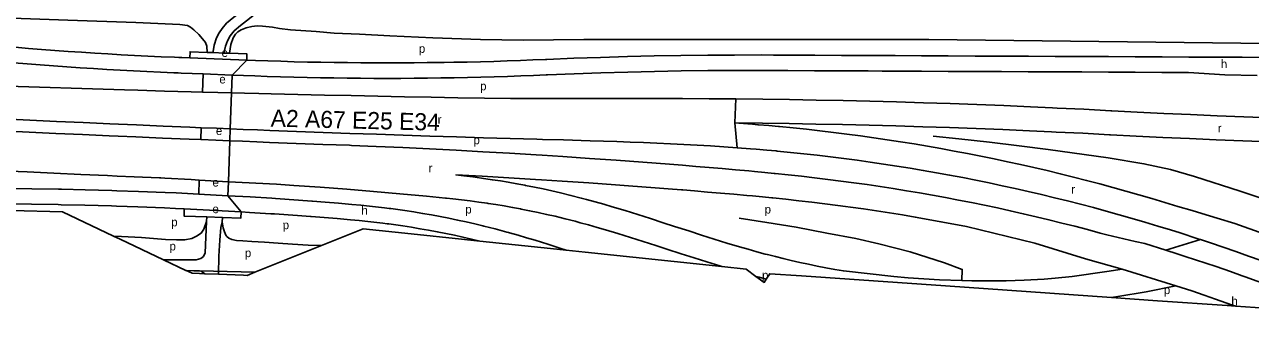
# Model space of a CAD drawing. Extents: x 161093 to 163177, y 379000 to 380904.
# Drawn here: x 162069 to 162643, y 379465 to 379601 of the extents above; entities that cross this region are included whole.
import ezdxf

# ---------------------------------------------------------------- set-up
doc = ezdxf.new("R2010")
doc.units = 0
for name, color, linetype in [('BLT_Basislijn', 7, 'Continuous'), ('BLT_Centroide', 7, 'Continuous'), ('BLT_Gemeentegrens', 7, 'Continuous'), ('BLT_Hoogspanningsmast_en_leidingen', 7, 'Continuous'), ('BLT_Straatnaam_hoofdweg', 7, 'Continuous'), ('BLT_Vlakafsluiter', 7, 'Continuous')]:
    doc.layers.add(name, color=color, linetype=linetype)

msp = doc.modelspace()

# ---------------------------------------------------------------- linework, layer by layer
at = {"layer": 'BLT_Basislijn'}
for p, q in [((162152.28, 379568.87), (162152.59, 379577.39)), ((162054.48, 379571.89), (162115.85, 379569.9)), ((162165.91, 379568.51), (162166.21, 379576.86)), ((162151.48, 379546.61), (162151.69, 379552.21)), ((162165.1, 379546.06), (162165.3, 379551.66)), ((162150.57, 379521.08), (162150.8, 379527.66)), ((162164.18, 379520.36), (162164.41, 379526.86)), ((162603.05, 379494.82), (162619.29, 379499.84)), ((162153.43, 379483.8), (162151.66, 379484.98)), ((162631.83, 379468.91), (162633.88, 379469.33))]:
    msp.add_line(p, q, dxfattribs=at)
for points in [[(162154.44, 379587.46), (162154.31, 379590.38), (162153.73, 379592.07), (162152.3, 379593.86), (162150.56, 379595.82), (162148.24, 379598.09), (162146.65, 379599.3), (162145.28, 379599.99), (162141.64, 379600.52), (162121.07, 379601.52), (162089.29, 379602.54), (162054.12, 379603.88), (162011.17, 379606.32), (161966.06, 379609.87), (161932.99, 379612.83), (161886.58, 379616.22), (161843.25, 379618.32), (161808.99, 379620.26), (161784.42, 379621.55), (161777.14, 379621.71)], [(162171.47, 379608.91), (162169.44, 379605.85), (162167, 379603.94), (162163.54, 379601.08), (162161.44, 379598.67), (162160.03, 379596.68), (162158.86, 379594.34), (162157.72, 379590.92), (162157.34, 379587.94), (162157.32, 379587.36)], [(162177.94, 379606.17), (162170.14, 379600.04), (162167.13, 379597.56), (162165.3, 379595.26), (162163.94, 379592.87), (162163, 379590.41), (162162.55, 379588.37), (162162.5, 379587.17)], [(162164.91, 379587.09), (162165.52, 379591.16), (162166.59, 379594.21), (162167.76, 379596.07), (162168.78, 379597.07), (162170.47, 379598.01), (162172.7, 379598.91), (162175.42, 379599.6), (162177.86, 379599.88), (162180.36, 379599.76), (162185.01, 379599.21), (162188.37, 379598.73), (162193.44, 379598.04), (162205.56, 379597.25), (162213.97, 379596.55), (162225.79, 379596.02), (162240.04, 379595.18), (162260.1, 379594.23), (162282.45, 379593.49), (162302.41, 379593.12), (162330.83, 379593.58), (162362.51, 379593.58), (162384.41, 379593.58), (162397.35, 379593.54), (162492.21, 379593.5), (162664.71, 379591.45)], [(162146.38, 379584.89), (162142.7, 379585.03), (162141.21, 379585.09), (162139.15, 379585.17), (162132.93, 379585.44), (162126.71, 379585.72), (162120.5, 379586.03), (162114.28, 379586.36), (162108.06, 379586.72), (162101.85, 379587.1), (162095.64, 379587.5), (162089.43, 379587.92), (162083.22, 379588.37), (162077.01, 379588.84), (162070.81, 379589.33), (162064.6, 379589.84)], [(162146.38, 379584.89), (162146.49, 379587.75), (162154.44, 379587.46)], [(162173, 379583.85), (162146.38, 379584.89)], [(162154.44, 379587.46), (162157.32, 379587.36)], [(162157.32, 379587.36), (162162.5, 379587.17)], [(162162.5, 379587.17), (162164.91, 379587.09)], [(162164.91, 379587.09), (162173.11, 379586.79), (162173, 379583.85)], [(162177.15, 379583.69), (162173, 379583.85)], [(162401.26, 379586.24), (162388.72, 379586.16), (162376.18, 379586.01), (162363.64, 379585.79), (162351.11, 379585.5), (162338.57, 379585.14), (162326.04, 379584.7), (162313.51, 379584.19), (162312.78, 379584.16), (162306.92, 379583.92), (162301.07, 379583.69), (162294.85, 379583.48), (162288.63, 379583.28), (162282.4, 379583.11), (162276.18, 379582.96), (162269.96, 379582.84), (162265.4, 379582.76), (162263.73, 379582.74), (162257.51, 379582.66), (162251.28, 379582.6), (162245.06, 379582.57), (162238.83, 379582.56), (162232.61, 379582.57), (162226.38, 379582.6), (162220.16, 379582.66), (162213.93, 379582.74), (162207.71, 379582.84), (162201.49, 379582.97), (162195.26, 379583.12), (162189.04, 379583.29), (162182.82, 379583.49), (162177.15, 379583.69)], [(162651.31, 379585.12), (162638.81, 379585.18), (162626.31, 379585.24), (162613.81, 379585.3), (162601.31, 379585.36), (162588.81, 379585.42), (162576.31, 379585.48), (162563.81, 379585.54), (162551.31, 379585.6), (162538.81, 379585.66), (162526.31, 379585.72), (162513.81, 379585.78), (162501.31, 379585.84), (162488.81, 379585.9), (162476.46, 379585.96), (162476.31, 379585.96), (162470.45, 379585.99), (162463.81, 379586.02), (162451.31, 379586.08), (162438.81, 379586.14), (162426.31, 379586.2), (162419.53, 379586.23), (162413.79, 379586.25), (162401.26, 379586.24)], [(162063.96, 379582.62), (162070.19, 379582.1), (162076.42, 379581.61), (162082.65, 379581.14), (162088.89, 379580.69), (162095.13, 379580.26), (162101.37, 379579.86), (162107.61, 379579.48), (162113.85, 379579.13), (162120.09, 379578.79), (162126.33, 379578.48), (162132.58, 379578.2), (162138.83, 379577.93), (162140.9, 379577.85), (162142.36, 379577.79), (162152.59, 379577.39)], [(162152.59, 379577.39), (162166.21, 379576.86)], [(162176.8, 379576.45), (162182.55, 379576.24), (162188.79, 379576.05), (162195.04, 379575.87), (162201.29, 379575.72), (162207.54, 379575.6), (162213.8, 379575.49), (162220.05, 379575.41), (162226.3, 379575.35), (162232.55, 379575.32), (162238.8, 379575.31), (162245.05, 379575.32), (162251.3, 379575.35), (162257.56, 379575.41), (162263.81, 379575.49), (162265.48, 379575.51), (162270.06, 379575.59), (162276.31, 379575.72), (162282.56, 379575.86), (162288.81, 379576.04), (162295.06, 379576.23), (162301.3, 379576.45), (162307.18, 379576.67), (162313.06, 379576.92), (162313.8, 379576.95), (162326.28, 379577.46), (162338.77, 379577.89), (162351.27, 379578.25), (162363.76, 379578.55), (162376.25, 379578.77), (162388.75, 379578.92), (162401.25, 379579), (162413.75, 379579), (162419.46, 379578.98), (162426.24, 379578.95), (162438.74, 379578.89), (162451.24, 379578.83), (162463.74, 379578.77), (162470.38, 379578.74), (162476.24, 379578.71), (162476.39, 379578.71), (162488.74, 379578.65), (162501.24, 379578.59), (162513.74, 379578.53), (162526.24, 379578.47), (162538.74, 379578.41), (162551.24, 379578.35), (162563.74, 379578.29), (162576.24, 379578.23), (162588.74, 379578.17), (162601.24, 379578.11), (162613.74, 379578.05), (162630.68, 379576.99), (162645.83, 379576.71)], [(162166.21, 379576.86), (162176.8, 379576.45)], [(162152.28, 379568.87), (162147.03, 379569.01), (162134.56, 379569.36), (162122.08, 379569.72), (162115.85, 379569.9)], [(162165.91, 379568.51), (162159.51, 379568.68), (162152.28, 379568.87)], [(162401.95, 379565.7), (162389.42, 379565.8), (162376.89, 379565.86), (162364.36, 379565.89), (162364.34, 379565.89), (162362.51, 379565.89), (162351.85, 379565.88), (162339.35, 379565.88), (162326.85, 379565.88), (162314.35, 379565.88), (162301.85, 379565.88), (162296.46, 379565.87), (162284.28, 379566.06), (162271.8, 379566.26), (162259.33, 379566.48), (162246.85, 379566.71), (162234.37, 379566.95), (162221.89, 379567.21), (162209.42, 379567.48), (162196.94, 379567.76), (162184.46, 379568.05), (162178.65, 379568.19), (162171.99, 379568.36), (162165.91, 379568.51)], [(162652.04, 379556.86), (162639.58, 379557.31), (162627.13, 379557.8), (162614.67, 379558.34), (162602.22, 379558.91), (162589.76, 379559.52), (162577.78, 379560.14), (162577.31, 379560.17), (162564.79, 379560.82), (162552.28, 379561.43), (162550.14, 379561.53), (162539.76, 379562), (162527.24, 379562.53), (162514.71, 379563.02), (162502.19, 379563.48), (162489.66, 379563.89), (162477.14, 379564.27), (162464.61, 379564.6), (162452.08, 379564.9), (162439.55, 379565.16), (162427.02, 379565.38), (162414.49, 379565.56), (162401.95, 379565.7)], [(162058.96, 379556.35), (162071.44, 379555.75), (162083.92, 379555.17), (162096.41, 379554.59), (162108.89, 379554.03), (162113.07, 379553.85)], [(162401.45, 379554.45), (162403.34, 379554.32), (162409.67, 379553.83), (162412.2, 379553.62), (162412.42, 379553.6), (162417.37, 379553.18), (162421.84, 379552.77), (162422.32, 379552.73), (162428.64, 379552.11), (162434.95, 379551.45), (162441.26, 379550.74), (162447.57, 379549.99), (162453.87, 379549.2), (162460.16, 379548.37), (162466.45, 379547.49), (162472.73, 379546.56), (162479, 379545.59), (162485.27, 379544.58), (162491.53, 379543.53), (162497.79, 379542.43), (162504.03, 379541.29), (162510.27, 379540.11), (162516.5, 379538.88), (162522.72, 379537.61), (162528.93, 379536.29), (162535.14, 379534.94), (162541.33, 379533.54), (162547.51, 379532.09), (162553.68, 379530.61), (162559.85, 379529.08), (162566, 379527.51), (162572.14, 379525.89), (162578.27, 379524.23), (162584.39, 379522.53), (162590.49, 379520.79), (162596.58, 379519.01), (162602.67, 379517.18), (162608.78, 379515.36), (162615.4, 379513.44), (162619.89, 379512.01), (162627.13, 379509.81), (162635.36, 379507.31)], [(162651.65, 379545.61), (162639.16, 379546.07), (162626.66, 379546.56), (162614.17, 379547.1), (162601.68, 379547.67), (162589.2, 379548.28), (162577.18, 379548.91), (162576.71, 379548.93), (162564.23, 379549.58), (162551.75, 379550.19), (162549.62, 379550.29), (162539.26, 379550.76), (162526.78, 379551.29), (162514.29, 379551.78), (162501.8, 379552.23), (162489.31, 379552.65), (162476.82, 379553.02), (162464.32, 379553.36), (162451.83, 379553.65), (162439.33, 379553.91), (162426.84, 379554.13), (162414.34, 379554.31), (162401.45, 379554.45)], [(162058.68, 379550.76), (162071.17, 379550.16), (162083.66, 379549.57), (162096.15, 379549), (162108.64, 379548.44), (162112.91, 379548.25)], [(162113.07, 379553.85), (162121.38, 379553.48), (162133.86, 379552.95), (162146.35, 379552.43), (162151.69, 379552.21)], [(162151.69, 379552.21), (162158.83, 379551.92), (162165.3, 379551.66)], [(162165.3, 379551.66), (162171.32, 379551.42), (162178, 379551.16), (162183.81, 379550.94), (162196.3, 379550.47), (162208.79, 379550.01), (162221.28, 379549.57), (162233.77, 379549.14), (162246.26, 379548.72), (162258.75, 379548.31), (162271.24, 379547.92), (162283.73, 379547.54), (162296.22, 379547.18), (162308.71, 379546.83), (162311.43, 379546.75), (162321.21, 379546.48), (162333.71, 379546.12), (162346.21, 379545.72), (162352.47, 379545.49), (162358.72, 379545.25), (162364.98, 379544.99), (162371.23, 379544.71), (162377.48, 379544.4), (162383.74, 379544.06), (162389.99, 379543.69), (162396.25, 379543.29), (162402.5, 379542.85)], [(162112.91, 379548.25), (162121.13, 379547.89), (162133.62, 379547.35), (162146.12, 379546.83), (162151.48, 379546.61)], [(162151.48, 379546.61), (162158.61, 379546.32), (162165.1, 379546.06)], [(162165.1, 379546.06), (162171.1, 379545.83), (162177.78, 379545.57), (162183.6, 379545.34), (162196.09, 379544.87), (162208.58, 379544.42), (162221.08, 379543.97), (162222.08, 379543.93), (162233.57, 379543.44), (162246.06, 379542.88), (162258.55, 379542.27), (162271.04, 379541.63), (162283.53, 379540.95), (162296.02, 379540.22), (162308.51, 379539.46), (162311.23, 379539.29), (162320.99, 379538.66), (162333.46, 379537.82), (162345.91, 379536.95), (162352.14, 379536.49), (162358.35, 379536.03), (162364.57, 379535.56), (162370.77, 379535.08), (162376.98, 379534.59), (162383.17, 379534.09), (162389.37, 379533.58), (162395.55, 379533.05), (162401.74, 379532.51), (162407.91, 379531.95), (162410.6, 379531.69), (162415.42, 379531.23), (162419.79, 379530.8), (162420.25, 379530.75), (162426.41, 379530.11), (162432.57, 379529.44), (162438.72, 379528.74), (162444.88, 379528), (162451.02, 379527.23), (162457.16, 379526.41), (162463.3, 379525.55), (162469.43, 379524.65), (162475.55, 379523.71), (162481.67, 379522.72), (162487.78, 379521.69), (162493.88, 379520.62), (162499.97, 379519.5), (162506.06, 379518.35), (162512.14, 379517.15), (162518.21, 379515.91), (162524.27, 379514.63), (162530.32, 379513.3), (162536.37, 379511.93), (162542.4, 379510.52), (162548.42, 379509.07), (162554.43, 379507.58), (162560.44, 379506.05), (162566.43, 379504.47), (162572.41, 379502.85), (162575.46, 379502.07), (162588.8, 379498.88), (162593.22, 379497.91)], [(162402.5, 379542.85), (162408.75, 379542.37), (162411.47, 379542.14), (162416.35, 379541.72), (162420.77, 379541.32), (162421.24, 379541.28), (162427.48, 379540.67), (162433.71, 379540.01), (162439.94, 379539.32), (162446.17, 379538.58), (162452.39, 379537.8), (162458.6, 379536.97), (162464.81, 379536.1), (162471.02, 379535.19), (162477.21, 379534.23), (162483.4, 379533.24), (162489.58, 379532.2), (162495.76, 379531.11), (162501.93, 379529.99), (162508.09, 379528.82), (162514.24, 379527.6), (162520.38, 379526.35), (162526.51, 379525.05), (162532.64, 379523.71), (162538.75, 379522.33), (162544.86, 379520.9), (162550.95, 379519.43), (162557.04, 379517.93), (162563.11, 379516.37), (162569.18, 379514.78), (162575.23, 379513.14), (162581.27, 379511.46), (162587.3, 379509.74), (162593.31, 379507.98), (162599.32, 379506.18), (162605.31, 379504.33), (162609.8, 379502.92)], [(162667.14, 379508.55), (162666.29, 379510.52), (162663.97, 379512.97), (162661.57, 379514.53), (162658.92, 379515.48), (162637.95, 379522.47), (162616.52, 379529.31), (162605.25, 379532.66), (162592.88, 379535.34), (162576.07, 379538.11), (162548.03, 379541.99), (162534.45, 379543.74), (162520.6, 379545.41), (162506.28, 379546.98), (162494.18, 379548.18)], [(162112.38, 379529.55), (162107.8, 379529.75), (162095.3, 379530.32), (162082.79, 379530.89), (162070.29, 379531.48), (162057.78, 379532.08)], [(162134.68, 379528.59), (162132.79, 379528.67), (162132.11, 379528.7), (162120.29, 379529.21), (162112.38, 379529.55)], [(162150.8, 379527.66), (162147.06, 379527.88), (162134.68, 379528.59)], [(162164.41, 379526.86), (162150.8, 379527.66)], [(162395.37, 379487.17), (162394.41, 379487.46), (162388.36, 379489.33), (162382.34, 379491.23), (162376.36, 379493.15), (162369.67, 379495.32), (162364.46, 379497.01), (162358.54, 379498.91), (162352.64, 379500.79), (162346.74, 379502.62), (162340.85, 379504.4), (162336.93, 379505.55), (162333, 379506.66), (162329.08, 379507.74), (162326.72, 379508.37), (162326.65, 379508.38), (162321.97, 379509.58), (162317.27, 379510.72), (162313.32, 379511.64), (162309.36, 379512.51), (162305.39, 379513.34), (162301.4, 379514.13), (162301.08, 379514.19), (162297.42, 379514.87), (162293.42, 379515.58), (162289.51, 379516.23), (162286.03, 379516.77), (162285.59, 379516.83), (162281.66, 379517.4), (162277.6, 379517.95), (162273.54, 379518.45), (162269.47, 379518.91), (162266.54, 379519.21), (162266.09, 379519.26), (162257.12, 379520.13), (162244.71, 379521.27), (162232.29, 379522.35), (162219.87, 379523.37), (162207.44, 379524.32), (162195.01, 379525.21), (162186.99, 379525.74), (162164.41, 379526.86)], [(162565.54, 379490.74), (162541.73, 379498.12), (162509.88, 379505.87), (162503.88, 379507.06), (162497.87, 379508.2), (162491.85, 379509.3), (162485.83, 379510.36), (162479.8, 379511.37), (162473.76, 379512.35), (162467.72, 379513.28), (162461.67, 379514.17), (162455.61, 379515.02), (162453.19, 379515.34), (162449.55, 379515.82), (162443.48, 379516.59), (162437.41, 379517.32), (162431.33, 379518.01), (162425.25, 379518.67), (162419.17, 379519.3), (162418.71, 379519.35), (162414.41, 379519.78), (162409.64, 379520.23), (162406.99, 379520.48), (162400.89, 379521.04), (162394.78, 379521.58), (162388.66, 379522.1), (162382.53, 379522.61), (162377.12, 379523.05), (162376.38, 379523.11), (162370.23, 379523.59), (162364.07, 379524.07), (162357.89, 379524.54), (162351.71, 379525), (162345.52, 379525.45), (162333.11, 379526.33), (162320.67, 379527.17), (162310.91, 379527.8), (162308.19, 379527.97), (162295.69, 379528.73), (162283.19, 379529.45), (162270.9, 379530.12), (162274.67, 379529.67), (162278.81, 379529.15), (162282.94, 379528.59), (162287.9, 379527.86), (162288.08, 379527.84), (162291.7, 379527.27), (162295.32, 379526.67), (162299.43, 379525.94), (162303.2, 379525.24), (162303.53, 379525.17), (162307.63, 379524.36), (162311.72, 379523.51), (162315.79, 379522.61), (162319.86, 379521.67), (162324.69, 379520.5), (162329.51, 379519.27), (162329.58, 379519.25), (162332, 379518.6), (162336.03, 379517.5), (162340.04, 379516.36), (162344.05, 379515.19), (162350.04, 379513.38), (162356.01, 379511.52), (162361.97, 379509.63), (162367.92, 379507.71), (162373.15, 379506.02), (162379.81, 379503.86), (162385.76, 379501.95), (162391.72, 379500.06), (162397.68, 379498.22), (162403.66, 379496.43), (162407.66, 379495.27), (162411.66, 379494.15), (162415.68, 379493.06), (162416.64, 379492.81), (162416.69, 379492.8), (162420.38, 379491.85), (162424.08, 379490.93), (162427.78, 379490.05), (162431.84, 379489.13), (162435.9, 379488.26), (162439.98, 379487.42), (162444.06, 379486.63), (162448.15, 379485.88), (162452.25, 379485.17), (162475.85, 379482.6), (162482.54, 379481.91), (162497.21, 379480.92), (162507.67, 379480.61)], [(162059.88, 379523.76), (162072.38, 379523.63), (162084.88, 379523.42), (162086.37, 379523.39), (162097.38, 379523.15), (162109.88, 379522.79), (162112.19, 379522.72)], [(162112.19, 379522.72), (162122.37, 379522.37), (162134.86, 379521.88), (162140.02, 379521.64), (162150.57, 379521.08)], [(162150.57, 379521.08), (162164.18, 379520.36)], [(162164.18, 379520.36), (162174.55, 379519.81)], [(162174.55, 379519.81), (162184.8, 379519.16), (162186.51, 379519.05), (162197.27, 379518.31), (162203.44, 379517.85), (162203.76, 379517.83), (162209.74, 379517.37), (162215.97, 379516.86), (162222.2, 379516.31), (162226.35, 379515.91), (162230.5, 379515.48), (162234.64, 379515.01), (162237.51, 379514.67), (162239.61, 379514.41), (162240.38, 379514.31), (162243.72, 379513.86), (162247.05, 379513.38), (162251.17, 379512.75), (162255.29, 379512.08), (162259.4, 379511.36), (162263.5, 379510.6), (162267.6, 379509.8), (162271.68, 379508.96), (162275.76, 379508.07), (162279.82, 379507.14), (162283.46, 379506.28), (162283.88, 379506.17), (162289.32, 379504.8), (162294.73, 379503.36), (162295.51, 379503.14), (162295.99, 379503.01), (162300, 379501.87), (162304, 379500.7), (162307.99, 379499.49), (162313.96, 379497.63), (162319.92, 379495.71), (162322.45, 379494.88)], [(162015.03, 379514.73), (162022.45, 379515.17), (162034.9, 379515.85), (162047.36, 379516.45), (162049.85, 379516.57), (162059.82, 379516.51), (162072.28, 379516.38), (162084.74, 379516.18), (162086.23, 379516.15), (162097.2, 379515.9), (162109.65, 379515.55), (162111.99, 379515.47)], [(162111.99, 379515.47), (162122.1, 379515.13), (162134.56, 379514.63), (162139.73, 379514.4), (162143.78, 379514.18)], [(162143.78, 379514.18), (162143.66, 379510.86), (162154.34, 379510.48)], [(162143.78, 379514.18), (162170.39, 379512.77)], [(162154.25, 379508.3), (162152.98, 379504.68), (162151.65, 379502.89), (162149.57, 379501.35), (162147.37, 379500.38), (162144.05, 379499.78), (162140.1, 379499.63), (162134.94, 379499.93), (162123.78, 379500.75), (162114.38, 379501.33), (162110.7, 379501.44)], [(162154.25, 379508.3), (162153.62, 379493.54), (162152.71, 379491.95), (162151.46, 379490.91), (162149.31, 379490.38), (162145.59, 379490.37)], [(162154.34, 379510.48), (162154.25, 379508.3)], [(162154.34, 379510.48), (162161.67, 379510.21)], [(162161.67, 379510.21), (162161.49, 379508.08)], [(162161.67, 379510.21), (162170.28, 379509.9), (162170.39, 379512.77)], [(162170.39, 379512.77), (162174.3, 379512.56)], [(162174.3, 379512.56), (162184.32, 379511.93), (162186.03, 379511.82), (162196.75, 379511.07), (162202.9, 379510.62), (162203.21, 379510.6), (162209.17, 379510.14), (162215.36, 379509.64), (162221.53, 379509.09), (162225.63, 379508.69), (162229.72, 379508.27), (162233.81, 379507.81), (162236.63, 379507.47), (162238.69, 379507.21), (162239.44, 379507.12), (162242.72, 379506.68), (162245.99, 379506.21), (162250.04, 379505.59), (162254.08, 379504.93), (162258.12, 379504.23), (162262.15, 379503.48), (162266.17, 379502.7), (162270.18, 379501.87), (162274.18, 379501), (162278.17, 379500.09), (162282.12, 379499.14)], [(162507.67, 379480.61), (162507.8, 379485.86), (162499.48, 379488.91), (162483.5, 379494.09), (162468.73, 379497.78), (162458.03, 379500.3), (162444.46, 379502.89), (162430.14, 379505.57), (162416.38, 379507.78), (162403.44, 379509.82)], [(162159.75, 379483.57), (162159.97, 379492.05), (162160.37, 379499.53), (162160.86, 379505.52), (162161.49, 379508.08)], [(162161.49, 379508.08), (162161.61, 379507.06), (162161.94, 379505.4), (162162.58, 379503.38), (162163.18, 379501.96), (162163.75, 379501.26), (162164.63, 379500.51), (162166.04, 379499.88), (162168.25, 379499.36), (162171.14, 379499.21), (162175.36, 379498.94), (162181.29, 379498.64), (162187.73, 379498.22), (162194.38, 379497.63), (162201.82, 379497.26), (162208.05, 379497.07)], [(162619.29, 379499.84), (162618.07, 379500.24), (162609.8, 379502.92)], [(162635.36, 379507.31), (162649.02, 379502.46)], [(162593.22, 379497.91), (162603.05, 379494.82)], [(162690.57, 379472.96), (162682.63, 379476.36), (162676.84, 379478.73), (162671.03, 379481.07), (162665.77, 379483.14), (162665.2, 379483.36), (162659.37, 379485.61), (162653.51, 379487.83), (162647.64, 379490), (162641.76, 379492.13), (162635.86, 379494.22), (162629.94, 379496.27), (162624.01, 379498.28), (162619.29, 379499.84)], [(162603.05, 379494.82), (162608.45, 379493.12), (162612.14, 379491.93), (162626.73, 379487.15), (162633.36, 379484.81), (162638.78, 379482.87), (162640.17, 379482.39), (162645.91, 379480.28), (162650.97, 379478.4), (162656.52, 379476.35), (162668.53, 379471.62), (162671.36, 379470.48), (162671.86, 379470.28), (162677.43, 379468.07)], [(162134.1, 379490.37), (162145.59, 379490.37)], [(162144.68, 379485.37), (162151.66, 379484.98)], [(162507.67, 379480.61), (162512.25, 379480.5), (162520.98, 379480.47), (162528.42, 379480.56), (162536.73, 379480.81), (162546.11, 379481.34), (162551.26, 379481.73), (162559.29, 379482.5), (162575.54, 379484.88), (162582.64, 379485.93)], [(162582.64, 379485.93), (162565.54, 379490.74)], [(162607.75, 379478.23), (162582.64, 379485.93)], [(162416.14, 379481.32), (162413.84, 379481.91), (162413.78, 379481.93), (162412.79, 379482.19), (162411.26, 379482.6)], [(162607.75, 379478.23), (162593.9, 379475.42), (162580.63, 379473.1), (162577.74, 379472.72)], [(162633.88, 379469.33), (162626.37, 379471.96), (162621.09, 379473.8), (162615.23, 379475.76), (162607.75, 379478.23)], [(162635.79, 379468.63), (162633.88, 379469.33)]]:
    msp.add_lwpolyline(points, dxfattribs=at)
at = {"layer": 'BLT_Gemeentegrens'}
for p, q in [((162153.43, 379483.8), (162150.97, 379483.9)), ((162159.75, 379483.57), (162153.43, 379483.8)), ((162171.46, 379483.13), (162159.75, 379483.57))]:
    msp.add_line(p, q, dxfattribs=at)
for points in [[(162015.03, 379514.73), (162086.74, 379512.78), (162110.7, 379501.44)], [(162208.05, 379497.07), (162221.24, 379502.37), (162227.48, 379504.87), (162249.94, 379502.52), (162273.53, 379500.05), (162282.12, 379499.14)], [(162134.1, 379490.37), (162113.75, 379500), (162110.7, 379501.44)], [(162208.05, 379497.07), (162176.73, 379484.5)], [(162282.12, 379499.14), (162315.08, 379495.66), (162322.45, 379494.88)], [(162322.45, 379494.88), (162331.37, 379493.94), (162395.37, 379487.17)], [(162144.58, 379485.42), (162134.1, 379490.37)], [(162144.68, 379485.37), (162144.58, 379485.42)], [(162150.97, 379483.9), (162147.53, 379484.02), (162144.68, 379485.37)], [(162395.37, 379487.17), (162406.66, 379485.98), (162411.26, 379482.6)], [(162176.73, 379484.5), (162173.17, 379483.07), (162171.46, 379483.13)], [(162411.26, 379482.6), (162415.14, 379479.76), (162416.14, 379481.32)], [(162416.14, 379481.32), (162417.75, 379483.85), (162432.59, 379482.91), (162500, 379478.2), (162577.74, 379472.72)], [(162577.74, 379472.72), (162599.2, 379471.21), (162631.83, 379468.91)], [(162631.83, 379468.91), (162635.79, 379468.63)], [(162635.79, 379468.63), (162644.88, 379467.97), (162683.02, 379465.21)]]:
    msp.add_lwpolyline(points, dxfattribs=at)
at = {"layer": 'BLT_Hoogspanningsmast_en_leidingen'}
msp.add_line((162144.58, 379485.42), (162176.73, 379484.5), dxfattribs=at)
at = {"layer": 'BLT_Vlakafsluiter'}
for p, q in [((162173, 379583.85), (162166.21, 379576.86)), ((162165.91, 379568.51), (162165.3, 379551.66)), ((162401.45, 379554.45), (162401.95, 379565.7)), ((162402.5, 379542.85), (162401.45, 379554.45)), ((162165.1, 379546.06), (162164.41, 379526.86)), ((162164.18, 379520.36), (162170.39, 379512.77))]:
    msp.add_line(p, q, dxfattribs=at)

# ---------------------------------------------------------------- texts
at = {"layer": 'BLT_Centroide'}
for s, p in [('p', (162253.55, 379587.25)), ('e', (162161.23, 379585.36)), ('h', (162628.87, 379580.09)), ('e', (162160.19, 379572.93)), ('p', (162282.22, 379569.72)), ('r', (162262.37, 379554.04)), ('e', (162158.58, 379548.79)), ('r', (162627.44, 379549.98)), ('p', (162279.09, 379544.46)), ('r', (162258.13, 379531.37)), ('e', (162156.97, 379524.65)), ('r', (162558.85, 379521.38)), ('e', (162156.97, 379512.19)), ('h', (162226.64, 379511.56)), ('p', (162275.28, 379512.01)), ('p', (162415.38, 379512.01)), ('p', (162137.67, 379506.04)), ('p', (162189.85, 379504.68)), ('p', (162136.87, 379494.75)), ('p', (162172.15, 379491.6)), ('p', (162414.15, 379481.2)), ('p', (162602.18, 379474.3)), ('h', (162633.77, 379469.05))]:
    msp.add_text(s, height=4, dxfattribs=at).set_placement(p)
at = {"layer": 'BLT_Straatnaam_hoofdweg'}
msp.add_text('A2 A67 E25 E34', height=8, rotation=358.57087, dxfattribs=at).set_placement((162184.16, 379552.75))

doc.saveas('drawing.dxf')
